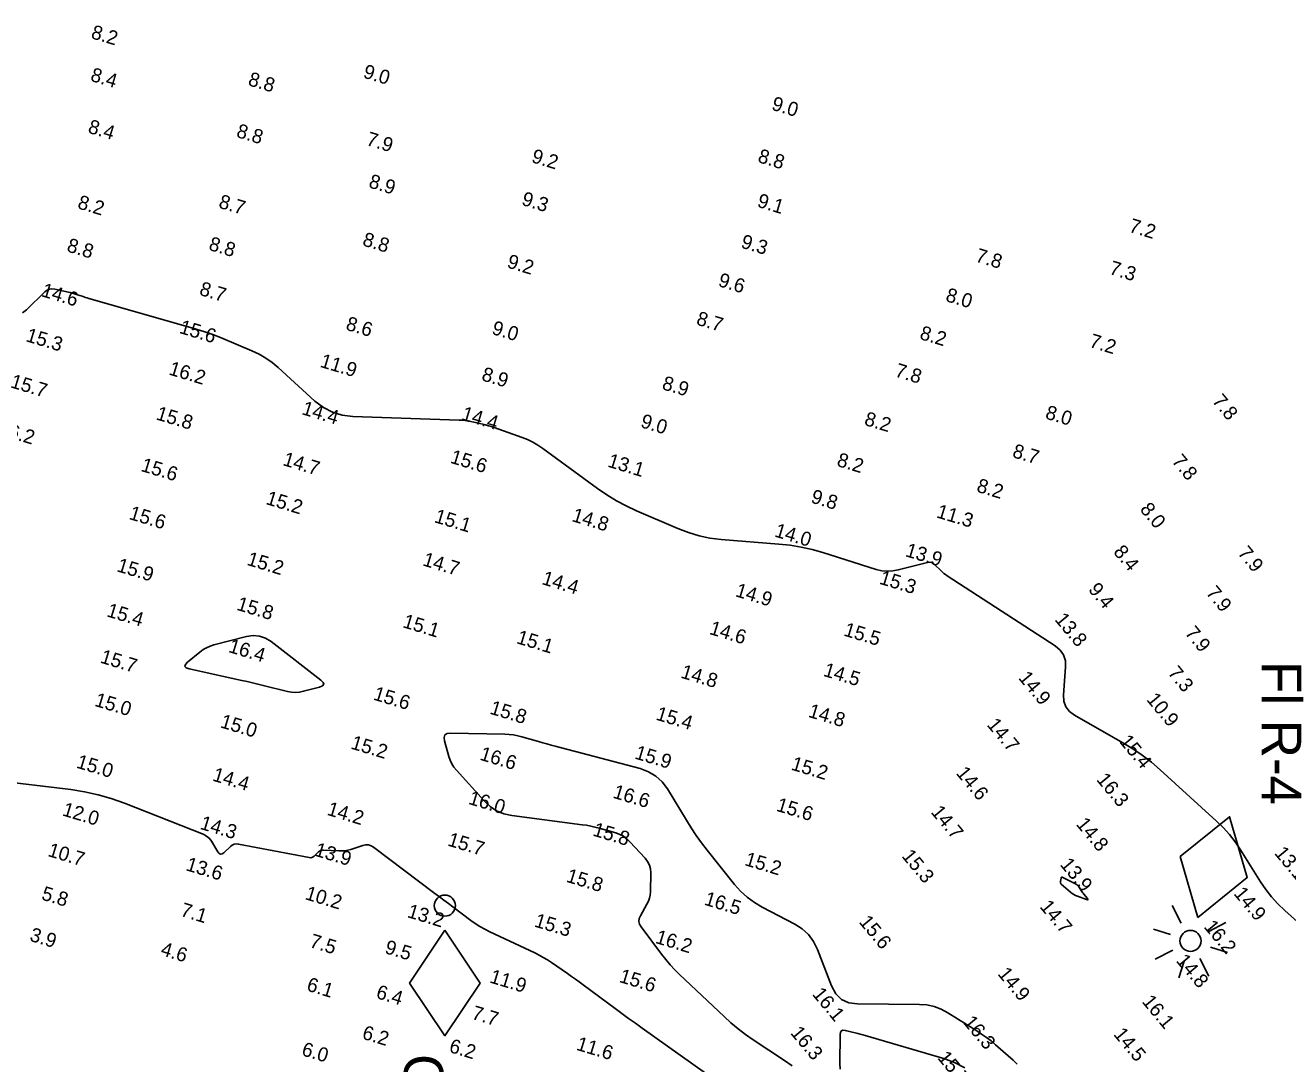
# Model space of a CAD drawing. Extents: x 824616 to 827440, y 158441 to 163197.
# Drawn here: x 826082.4 to 826529.7, y 161220.6 to 161588.6 of the extents above; entities that cross this region are included whole.
import ezdxf

# ---------------------------------------------------------------- set-up
doc = ezdxf.new("R2010")
doc.units = 0
for name, color, linetype in [('V-CHAN-CONT-EL14', 7, 'Continuous'), ('V-CHAN-CONT-EL16', 7, 'Continuous'), ('V-CHAN-NAID', 7, 'Continuous'), ('V-TOPO-SOUN', 7, 'Continuous')]:
    doc.layers.add(name, color=color, linetype=linetype)

msp = doc.modelspace()

# ---------------------------------------------------------------- linework, layer by layer
at = {"layer": 'V-CHAN-CONT-EL14'}
for points in [[(826538.78, 161265.84), (826528.61, 161274.92), (826526.2, 161277.23), (826523.97, 161279.69), (826521.92, 161282.3), (826520.05, 161285.07), (826512.92, 161296.43), (826511.05, 161299.19), (826509.01, 161301.81), (826506.79, 161304.29), (826504.4, 161306.62), (826484.47, 161324.76), (826481.38, 161327.43), (826478.15, 161329.91), (826474.79, 161332.21), (826471.3, 161334.34), (826454.19, 161344.1), (826452.35, 161345.46), (826451.09, 161347.13), (826450.41, 161349.11), (826450.29, 161351.39), (826450.99, 161361.14), (826450.89, 161363.44), (826450.23, 161365.46), (826449.01, 161367.21), (826447.24, 161368.68), (826409.06, 161393.5), (826408.44, 161393.93), (826407.84, 161394.38), (826407.27, 161394.87), (826406.72, 161395.38), (826404.58, 161397.5), (826404.02, 161397.94), (826403.41, 161398.21), (826402.76, 161398.29), (826402.05, 161398.2), (826391.69, 161395.58), (826389.72, 161395.22), (826387.76, 161395.14), (826385.81, 161395.33), (826383.87, 161395.8), (826364.95, 161401.74), (826361.13, 161402.83), (826357.26, 161403.69), (826353.36, 161404.34), (826349.41, 161404.77), (826328.91, 161406.42), (826324.97, 161406.9), (826321.1, 161407.7), (826317.31, 161408.81), (826313.6, 161410.24), (826298.92, 161416.58), (826295.31, 161418.26), (826291.81, 161420.14), (826288.42, 161422.21), (826285.13, 161424.47), (826265.75, 161438.68), (826264.02, 161439.86), (826262.21, 161440.89), (826260.34, 161441.8), (826258.39, 161442.56), (826248.51, 161446.04), (826247.5, 161446.38), (826246.49, 161446.69), (826245.47, 161446.97), (826244.44, 161447.22), (826240.29, 161448.15), (826239.25, 161448.36), (826238.21, 161448.52), (826237.16, 161448.63), (826236.1, 161448.69), (826198.44, 161449.95), (826194.7, 161450.39), (826191.22, 161451.45), (826187.98, 161453.13), (826185, 161455.43), (826172.01, 161467.31), (826169.88, 161469.1), (826167.61, 161470.69), (826165.22, 161472.07), (826162.7, 161473.26), (826152.35, 161477.59), (826149.75, 161478.63), (826147.13, 161479.6), (826144.47, 161480.48), (826141.79, 161481.29), (826104.87, 161491.83), (826104.26, 161492), (826103.66, 161492.18), (826103.06, 161492.37), (826102.47, 161492.57), (826100.08, 161493.36), (826099.48, 161493.55), (826098.88, 161493.73), (826098.27, 161493.89), (826097.66, 161494.03), (826092.81, 161495.11), (826091.83, 161495.21), (826090.92, 161495.08), (826090.08, 161494.71), (826089.3, 161494.11), (826082.79, 161487.77), (826081.39, 161486.66)], [(826070.65, 161321.11), (826098.51, 161317.75), (826103.37, 161317), (826108.15, 161315.95), (826112.86, 161314.6), (826117.49, 161312.94), (826145.35, 161301.93), (826146.25, 161301.5), (826147.03, 161300.94), (826147.72, 161300.26), (826148.3, 161299.46), (826150.62, 161295.67), (826151.07, 161295.13), (826151.57, 161294.9), (826152.1, 161294.99), (826152.69, 161295.39), (826155.1, 161297.63), (826155.73, 161298.1), (826156.41, 161298.39), (826157.14, 161298.5), (826157.92, 161298.44), (826183, 161293.65), (826183.5, 161293.61), (826183.95, 161293.69), (826184.37, 161293.88), (826184.75, 161294.19), (826186.21, 161295.66), (826186.6, 161295.98), (826187.02, 161296.2), (826187.48, 161296.32), (826187.98, 161296.34), (826193.48, 161296.03), (826194.56, 161296.02), (826195.63, 161296.1), (826196.68, 161296.29), (826197.73, 161296.58), (826201.94, 161297.95), (826202.97, 161298.16), (826203.95, 161298.12), (826204.9, 161297.84), (826205.8, 161297.3), (826227.54, 161280.91), (826229.12, 161279.72), (826230.7, 161278.53), (826232.29, 161277.34), (826233.87, 161276.16), (826240.2, 161271.41), (826241.81, 161270.27), (826243.47, 161269.21), (826245.18, 161268.24), (826246.94, 161267.36), (826262.88, 161259.85), (826264.42, 161259.09), (826265.92, 161258.27), (826267.38, 161257.38), (826268.82, 161256.44), (826274.48, 161252.55), (826275.89, 161251.57), (826277.29, 161250.58), (826278.68, 161249.58), (826280.07, 161248.56), (826291.43, 161240.14), (826293.79, 161238.41), (826296.16, 161236.68), (826298.53, 161234.97), (826300.92, 161233.26), (826323.44, 161217.25)]]:
    msp.add_lwpolyline(points, dxfattribs=at)
msp.add_lwpolyline([(826449.15, 161284.65), (826449.27, 161284.42), (826449.45, 161284.22), (826452.74, 161281.36), (826453.3, 161280.92), (826453.9, 161280.53), (826454.53, 161280.2), (826455.2, 161279.93), (826458.43, 161278.8), (826458.77, 161278.71), (826458.93, 161278.75), (826458.91, 161278.91), (826458.71, 161279.2), (826457.43, 161280.74), (826457.19, 161281.04), (826456.97, 161281.34), (826456.75, 161281.64), (826456.55, 161281.96), (826455.76, 161283.23), (826455.54, 161283.53), (826455.29, 161283.8), (826455.01, 161284.02), (826454.69, 161284.21), (826450, 161286.63), (826449.76, 161286.71), (826449.58, 161286.68), (826449.44, 161286.56), (826449.36, 161286.32), (826449.13, 161285.18), (826449.1, 161284.9)], close=True, dxfattribs=at)
at = {"layer": 'V-CHAN-CONT-EL16'}
msp.add_lwpolyline([(826146.56, 161368.03), (826147.83, 161368.59), (826149.16, 161369.01), (826160.8, 161371.99), (826163.14, 161372.34), (826165.37, 161372.16), (826167.49, 161371.44), (826169.5, 161370.2), (826187.09, 161356.58), (826187.92, 161355.75), (826188.12, 161355.06), (826187.67, 161354.49), (826186.58, 161354.06), (826180.95, 161352.58), (826179.54, 161352.3), (826178.13, 161352.2), (826176.72, 161352.28), (826175.31, 161352.54), (826166.71, 161354.67), (826164.81, 161355.13), (826162.9, 161355.58), (826160.99, 161356.02), (826159.07, 161356.44), (826140.48, 161360.5), (826139.41, 161360.88), (826138.95, 161361.4), (826139.12, 161362.08), (826139.89, 161362.9), (826144.25, 161366.51), (826145.37, 161367.34)], close=True, dxfattribs=at)
for points in [[(826354.07, 161219.84), (826351.36, 161221.74), (826340.3, 161229.08), (826337.59, 161230.97), (826334.95, 161232.98), (826332.41, 161235.09), (826329.96, 161237.31), (826314.21, 161252.2), (826312.5, 161253.89), (826310.86, 161255.65), (826309.3, 161257.48), (826307.81, 161259.38), (826300.55, 161269.09), (826300.01, 161270.05), (826299.79, 161271.02), (826299.89, 161272.02), (826300.31, 161273.03), (826302.66, 161277.13), (826303.18, 161278.17), (826303.56, 161279.25), (826303.79, 161280.37), (826303.88, 161281.54), (826303.97, 161288.2), (826303.87, 161289.65), (826303.5, 161291.01), (826302.87, 161292.27), (826301.99, 161293.43), (826296.62, 161299.29), (826295.53, 161300.33), (826294.33, 161301.19), (826293.02, 161301.88), (826291.6, 161302.39), (826285.7, 161304.08), (826284.22, 161304.47), (826282.73, 161304.81), (826281.23, 161305.09), (826279.71, 161305.32), (826254.71, 161308.61), (826251.92, 161309.21), (826249.37, 161310.27), (826247.05, 161311.77), (826244.97, 161313.71), (826235.11, 161324.62), (826234.22, 161325.72), (826233.48, 161326.91), (826232.88, 161328.17), (826232.43, 161329.51), (826230.93, 161335.05), (826230.78, 161336.26), (826231.08, 161337.11), (826231.84, 161337.61), (826233.05, 161337.76), (826252.32, 161337.37), (826253.85, 161337.29), (826255.36, 161337.11), (826256.85, 161336.83), (826258.34, 161336.46), (826264.24, 161334.78), (826265.71, 161334.36), (826267.19, 161333.95), (826268.67, 161333.55), (826270.15, 161333.15), (826300.25, 161325.17), (826303.2, 161324.1), (826305.79, 161322.54), (826308.01, 161320.5), (826309.87, 161317.97), (826316.6, 161306.89), (826318.32, 161304.15), (826320.13, 161301.47), (826322.03, 161298.85), (826324.01, 161296.29), (826333.7, 161284.15), (826335.83, 161281.75), (826338.17, 161279.61), (826340.73, 161277.72), (826343.49, 161276.1), (826354.99, 161270.11), (826357.64, 161268.42), (826359.88, 161266.35), (826361.68, 161263.9), (826363.06, 161261.07), (826368.05, 161248.15), (826369.54, 161245.39), (826371.57, 161243.4), (826374.14, 161242.2), (826377.26, 161241.78), (826399.17, 161241.62), (826401.84, 161241.42), (826404.4, 161240.87), (826406.85, 161239.96), (826409.21, 161238.69), (826419.51, 161232.25), (826421.24, 161231.11), (826422.92, 161229.92), (826424.56, 161228.66), (826426.15, 161227.33), (826432.41, 161221.89), (826433.8, 161220.45)], [(826415.28, 161219.17), (826411.9, 161220.97), (826408.23, 161222.31), (826380, 161230.56), (826379.12, 161230.81), (826378.23, 161231.05), (826377.35, 161231.29), (826376.46, 161231.51), (826372.89, 161232.39), (826372.1, 161232.47), (826371.54, 161232.26), (826371.2, 161231.77), (826371.08, 161230.99), (826370.96, 161220.71), (826371.07, 161218.73)]]:
    msp.add_lwpolyline(points, dxfattribs=at)
at = {"layer": 'V-CHAN-NAID'}
for p, q in [((826491.97, 161270.39), (826488.72, 161276.64)), ((826501.49, 161267.39), (826507.74, 161270.64)), ((826488.1, 161266.38), (826482.15, 161268.25)), ((826482.72, 161257.62), (826488.97, 161260.87)), ((826502.36, 161261.88), (826508.31, 161260.01)), ((826492.98, 161257), (826491.11, 161251.05)), ((826501.74, 161251.62), (826498.49, 161257.87))]:
    msp.add_line(p, q, dxfattribs=at)
for points in [[(826497.85, 161272.45), (826515.37, 161286.54), (826509.1, 161308.12), (826491.59, 161294.04)], [(826231.03, 161267.89), (826218.56, 161249.19), (826231.03, 161230.49), (826243.5, 161249.19)]]:
    msp.add_lwpolyline(points, close=True, dxfattribs=at)
for centre in [(826231.03, 161276.62), (826495.23, 161264.13)]:
    msp.add_circle(centre, 3.74, dxfattribs=at)

# ---------------------------------------------------------------- texts
for s, p in [('Fl R-4', (826520.49, 161363.27)), ('GC-5', (826216.49, 161224.02))]:
    msp.add_text(s, height=14, rotation=270, dxfattribs=at).set_placement(p)
at = {"layer": 'V-TOPO-SOUN'}
for s, rotation, p in [('8.2', 343.2, (826105.37, 161584.11)), ('8.4', 343.2, (826105.16, 161569.01)), ('9.0', 343.2, (826201.78, 161570.14)), ('8.8', 343.2, (826161.02, 161567.45)), ('9.0', 343.2, (826346.49, 161558.76)), ('8.4', 343.2, (826104.27, 161550.62)), ('8.8', 343.2, (826156.85, 161549.1)), ('7.9', 343.2, (826202.89, 161546.24)), ('9.2', 343.2, (826261.43, 161540.16)), ('8.8', 343.2, (826341.61, 161540.2)), ('8.9', 343.2, (826203.74, 161531.24)), ('8.2', 343.2, (826100.59, 161523.81)), ('8.7', 343.2, (826150.57, 161524.04)), ('9.3', 343.2, (826257.93, 161525.03)), ('9.1', 343.2, (826341.41, 161524.37)), ('7.2', 343.2, (826473.14, 161515.52)), ('8.8', 343.2, (826201.56, 161510.66)), ('8.8', 343.2, (826096.78, 161508.55)), ('8.8', 343.2, (826147.05, 161509.09)), ('9.3', 343.2, (826335.63, 161509.88)), ('9.2', 343.2, (826252.77, 161502.84)), ('7.8', 343.2, (826418.73, 161504.95)), ('7.3', 343.2, (826466.14, 161500.55)), ('8.7', 343.2, (826143.75, 161493.16)), ('9.6', 343.2, (826327.57, 161496.26)), ('14.6 ', 343.2, (826087.78, 161492.64)), ('8.0', 343.2, (826408.16, 161490.94)), ('15.6 ', 343.2, (826136.64, 161479.62)), ('8.6', 343.2, (826195.64, 161480.8)), ('9.0', 343.2, (826247.35, 161479.28)), ('8.7', 343.2, (826319.83, 161482.62)), ('15.3 ', 343.2, (826082.28, 161476.71)), ('8.2', 343.2, (826398.98, 161477.5)), ('7.2', 343.2, (826459.08, 161474.68)), ('11.9 ', 343.2, (826186.53, 161467.61)), ('16.2 ', 343.2, (826132.92, 161464.91)), ('8.9', 343.2, (826243.74, 161462.87)), ('7.8', 343.2, (826390.19, 161464.22)), ('15.7 ', 343.2, (826076.81, 161460.37)), ('8.9', 343.2, (826307.69, 161459.72)), ('7.8', 309.7, (826502.67, 161455.35)), ('15.8 ', 343.2, (826128.41, 161448.99)), ('14.4 ', 343.2, (826180.07, 161450.83)), ('14.4 ', 343.2, (826236.63, 161448.94)), ('8.0', 343.2, (826443.48, 161449.33)), ('16.2 ', 343.2, (826072.38, 161443.73)), ('9.0', 343.2, (826300.07, 161446.26)), ('8.2', 343.2, (826379.34, 161447.06)), ('8.7', 343.2, (826431.83, 161435.65)), ('15.6 ', 343.2, (826123.05, 161430.72)), ('14.7 ', 343.2, (826173.32, 161432.79)), ('15.6 ', 343.2, (826232.65, 161433.62)), ('13.1 ', 343.2, (826288.41, 161432.24)), ('8.2', 343.2, (826369.62, 161432.53)), ('7.8', 309.7, (826488.34, 161434.04)), ('8.2', 343.2, (826419.14, 161423.4)), ('15.2 ', 343.2, (826167.32, 161418.99)), ('9.8', 343.2, (826360.43, 161419.53)), ('15.6 ', 343.2, (826118.83, 161413.69)), ('15.1 ', 343.2, (826227.01, 161412.57)), ('14.8 ', 343.2, (826275.74, 161412.95)), ('11.3 ', 343.2, (826404.93, 161414.27)), ('8.0', 309.7, (826477.08, 161416.96)), ('14.0 ', 343.2, (826347.56, 161407.5)), ('13.9 ', 343.2, (826393.91, 161400.52)), ('8.4', 309.7, (826467.66, 161401.87)), ('7.9', 309.7, (826511.74, 161401.48)), ('15.9 ', 343.2, (826114.52, 161395.17)), ('15.2 ', 343.2, (826160.59, 161397.44)), ('14.7 ', 343.2, (826222.87, 161397.26)), ('14.4 ', 343.2, (826265.11, 161390.62)), ('15.3 ', 343.2, (826384.69, 161390.75)), ('14.9 ', 343.2, (826333.68, 161386.32)), ('9.4', 309.7, (826458.79, 161388.55)), ('7.9', 309.7, (826500.49, 161387.38)), ('15.8 ', 343.2, (826156.95, 161381.52)), ('15.4 ', 343.2, (826110.91, 161379.21)), ('15.1 ', 343.2, (826215.8, 161375.34)), ('14.6 ', 343.2, (826324.47, 161372.94)), ('15.5 ', 343.2, (826372.07, 161372.38)), ('13.8 ', 309.7, (826446.9, 161377.92)), ('15.1 ', 343.2, (826256.14, 161369.67)), ('7.9', 309.7, (826493, 161373.14)), ('16.4 ', 343.2, (826154.08, 161366.56)), ('15.7 ', 343.2, (826108.64, 161362.8)), ('14.8 ', 343.2, (826314.35, 161357.47)), ('14.5 ', 343.2, (826364.86, 161358.1)), ('14.9 ', 309.7, (826434.02, 161357.25)), ('7.3', 309.7, (826486.95, 161359)), ('15.6 ', 343.2, (826205.39, 161349.69)), ('15.0 ', 343.2, (826106.63, 161347.48)), ('10.9 ', 309.7, (826479.4, 161349.58)), ('15.8 ', 343.2, (826246.66, 161344.7)), ('15.4 ', 343.2, (826305.51, 161342.59)), ('14.8 ', 343.2, (826359.52, 161343.58)), ('15.0 ', 343.2, (826151.15, 161339.87)), ('14.7 ', 309.7, (826422.86, 161340.62)), ('15.2 ', 343.2, (826197.41, 161332.33)), ('15.4 ', 309.7, (826469.78, 161334.73)), ('16.6 ', 343.2, (826243.09, 161328.39)), ('15.9 ', 343.2, (826298.01, 161328.81)), ('15.0 ', 343.2, (826100.18, 161325.57)), ('15.2 ', 343.2, (826353.42, 161324.87)), ('14.4 ', 343.2, (826148.42, 161320.99)), ('14.6 ', 309.7, (826411.93, 161323.49)), ('16.3 ', 309.7, (826461.68, 161321.19)), ('16.6 ', 343.2, (826290.28, 161314.92)), ('16.0 ', 343.2, (826239.11, 161312.74)), ('15.6 ', 343.2, (826348.17, 161310.3)), ('12.0 ', 343.2, (826095.19, 161308.66)), ('14.2 ', 343.2, (826189, 161308.86)), ('14.7 ', 309.7, (826403.02, 161309.69)), ('14.3 ', 343.2, (826143.98, 161303.88)), ('15.8 ', 343.2, (826283.15, 161301.52)), ('14.8 ', 309.7, (826454.45, 161305.4)), ('15.7 ', 343.2, (826231.71, 161297.98)), ('10.7 ', 343.2, (826090.07, 161294.27)), ('13.9 ', 343.2, (826184.58, 161294.39)), ('15.3 ', 309.7, (826392.67, 161294.12)), ('13.1 ', 309.7, (826524.73, 161295.14)), ('13.6 ', 343.2, (826138.97, 161289.22)), ('15.2 ', 343.2, (826336.97, 161291.03)), ('13.9 ', 309.7, (826448.79, 161291.1)), ('15.8 ', 343.2, (826273.75, 161285.14)), ('5.8', 343.2, (826087.79, 161278.87)), ('10.2 ', 343.2, (826181.22, 161278.96)), ('14.9 ', 309.7, (826510.32, 161280.8)), ('16.5 ', 343.2, (826322.64, 161277.01)), ('14.7 ', 309.7, (826441.59, 161276.16)), ('7.1', 343.2, (826137.04, 161273.05)), ('13.2 ', 343.2, (826217.44, 161272.6)), ('15.3 ', 343.2, (826262.45, 161269.28)), ('15.6 ', 309.7, (826377.52, 161270.76)), ('16.2 ', 309.7, (826499.73, 161269.05)), ('3.9', 343.2, (826083.63, 161264.25)), ('7.5', 343.2, (826182.78, 161262.02)), ('9.5', 343.2, (826209.44, 161259.84)), ('16.2 ', 343.2, (826305.32, 161263.45)), ('4.6', 343.2, (826130.03, 161259.17)), ('14.8 ', 309.7, (826489.9, 161257.01)), ('6.1', 343.2, (826181.78, 161246.61)), ('11.9 ', 343.2, (826246.6, 161249.45)), ('15.6 ', 343.2, (826292.52, 161249.62)), ('14.9 ', 309.7, (826426.69, 161252.35)), ('6.4', 343.2, (826206.36, 161243.94)), ('16.1 ', 309.7, (826360.98, 161245.17)), ('16.1 ', 309.7, (826477.82, 161242.52)), ('7.7', 343.2, (826240.25, 161236.57)), ('6.2', 343.2, (826201.42, 161229.54)), ('16.3 ', 309.7, (826353.24, 161231.44)), ('16.3 ', 309.7, (826414.45, 161235.19)), ('14.5 ', 309.7, (826467.73, 161230.93)), ('6.2', 343.2, (826232.23, 161224.82)), ('11.6 ', 343.2, (826277.3, 161225.59)), ('6.0', 343.2, (826179.98, 161223.67)), ('15.7 ', 309.7, (826405.35, 161222.62))]:
    msp.add_text(s, height=5, rotation=rotation, dxfattribs=at).set_placement(p)

doc.saveas('drawing.dxf')
